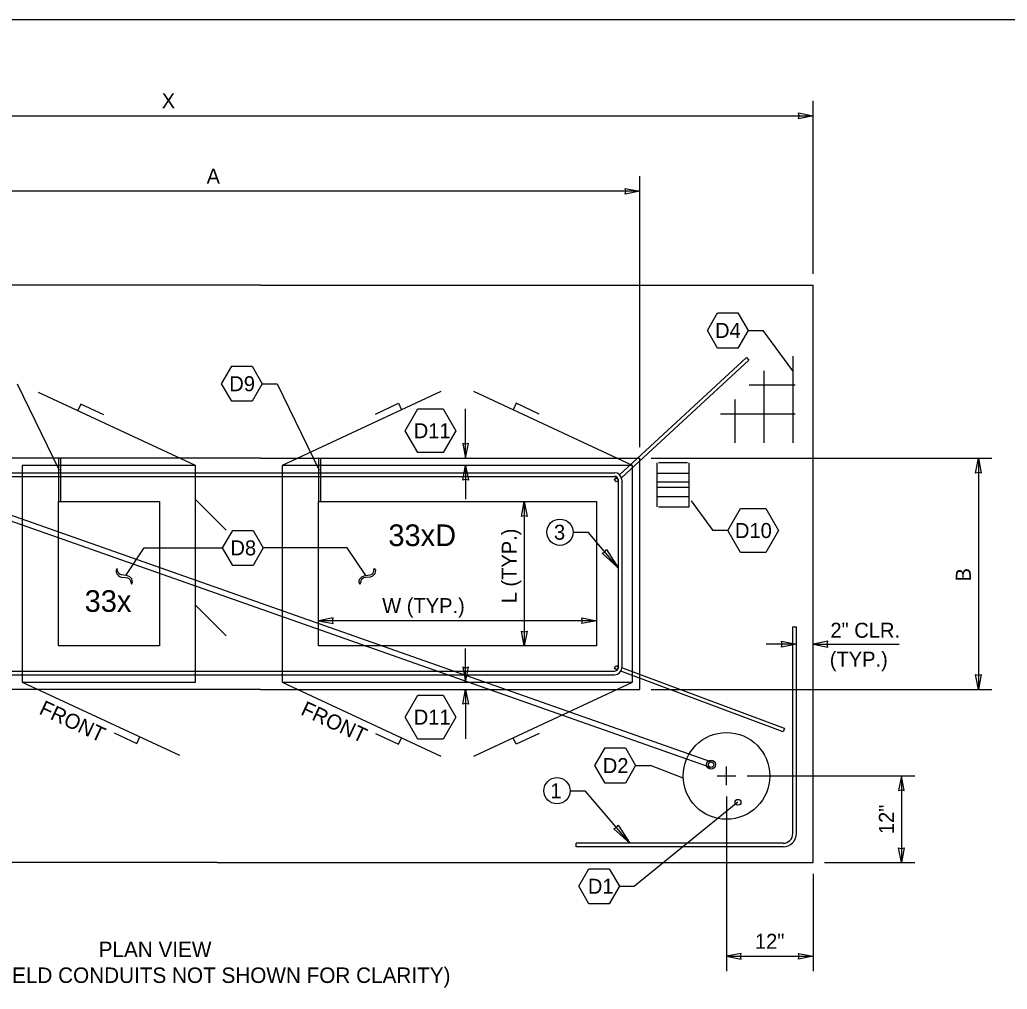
# Model space of a CAD drawing. Extents: x 99862 to 103151, y 100000 to 117076.
# Drawn here: x 100667 to 101719, y 113042 to 114076 of the extents above; entities that cross this region are included whole.
import ezdxf

# ---------------------------------------------------------------- set-up
doc = ezdxf.new("R2010")
doc.units = 0
for name, color, linetype in [('Default', 7, 'Continuous'), ('Level 1', 7, 'Continuous'), ('Level 10', 7, 'Continuous'), ('Level 11', 7, 'Continuous'), ('Level 14', 7, 'Continuous'), ('Level 15', 7, 'Continuous'), ('Level 20', 7, 'Continuous'), ('Level 30', 7, 'Continuous'), ('Level 6', 7, 'Continuous')]:
    doc.layers.add(name, color=color, linetype=linetype)

msp = doc.modelspace()

# ---------------------------------------------------------------- linework, layer by layer
at = {"layer": 'Default'}
for p, q in [((101441.3, 113715.5), (101305.9, 113590.5)), ((101441.3, 113715.5), (101443.9, 113712.7)), ((101443.9, 113712.7), (101308, 113587.3)), ((100442.7, 113592.6), (101300.7, 113592.6)), ((100442.7, 113588.7), (101300.7, 113588.7)), ((101303.1, 113587.9), (101301.3, 113586.3)), ((101304.5, 113584), (101303.9, 113583.5)), ((101304.5, 113584.9), (101304.5, 113384.8)), ((101308.4, 113584.9), (101308.4, 113384.8)), ((101490.6, 113207.9), (101490.6, 113428.3)), ((101490.6, 113428.3), (101494.4, 113428.3)), ((101494.4, 113207.9), (101494.4, 113428.3)), ((100442.7, 113381), (101300.7, 113381)), ((101303.7, 113382.4), (101301.9, 113383)), ((101304.5, 113386.2), (101303.3, 113386.6)), ((101480.3, 113316.3), (101307.4, 113381)), ((101481.7, 113319.9), (101308.4, 113384.7)), ((100442.7, 113377.1), (101300.7, 113377.1)), ((101481.7, 113319.9), (101480.3, 113316.3)), ((101480.3, 113197.6), (101260, 113197.6)), ((101260, 113193.8), (101260, 113197.6)), ((101480.3, 113193.8), (101260, 113193.8))]:
    msp.add_line(p, q, dxfattribs=at)
for centre in [(101302.6, 113584.9), (101302.6, 113384.8)]:
    msp.add_circle(centre, 1.92, dxfattribs=at)
for centre, radius, start, end in [((101300.7, 113584.9), 7.7, 0, 90), ((101300.7, 113584.9), 3.85, 0, 90), ((101300.7, 113384.8), 7.7, 270, 0), ((101300.7, 113384.8), 3.85, 270, 360), ((101480.3, 113207.9), 10.3, 270, 0), ((101480.3, 113207.9), 14.1, 270, 0)]:
    msp.add_arc(centre, radius, start, end, dxfattribs=at)
at = {"layer": 'Level 1'}
for p, q in [((101490.5, 113716.7), (101490.5, 113686)), ((101459.7, 113701.4), (101459.7, 113686)), ((100251, 113684.5), (101402.6, 113278.7)), ((101404.5, 113284.1), (100252.9, 113689.9)), ((101459.7, 113686), (101444.3, 113686)), ((101490.5, 113686), (101459.7, 113686)), ((101459.7, 113686), (101459.7, 113655.2)), ((101490.5, 113686), (101490.5, 113655.2)), ((101493.1, 113686), (101490.5, 113686)), ((101115.8, 113679.1), (100946.7, 113600.3)), ((101319.9, 113600.3), (101150.8, 113679.1)), ((101046.2, 113655.2), (101070.7, 113666.6)), ((101070.7, 113666.6), (101073.9, 113659.6)), ((101196, 113666.6), (101192.8, 113659.6)), ((101220.4, 113655.2), (101196, 113666.6)), ((101428.9, 113670.6), (101428.9, 113655.2)), ((101428.9, 113655.2), (101413.6, 113655.2)), ((101459.7, 113655.2), (101428.9, 113655.2)), ((101428.9, 113655.2), (101428.9, 113624.4)), ((101490.5, 113655.2), (101459.7, 113655.2)), ((101459.7, 113655.2), (101459.7, 113624.4)), ((101490.5, 113655.2), (101490.5, 113624.4)), ((101493.1, 113655.2), (101490.5, 113655.2)), ((100946.7, 113369.4), (101115.8, 113290.6)), ((101150.8, 113290.6), (101319.9, 113369.4)), ((101046.2, 113314.5), (101070.7, 113303.1)), ((101070.7, 113303.1), (101073.9, 113310.1)), ((101196, 113303.1), (101192.8, 113310.1)), ((101220.4, 113314.5), (101196, 113303.1))]:
    msp.add_line(p, q, dxfattribs=at)
for points in [[(99862, 111999.5), (103151, 111999.5), (103151, 114075.5), (99862, 114075.5)], [(100946.7, 113369.4), (101319.9, 113369.4), (101319.9, 113600.3), (100946.7, 113600.3)]]:
    msp.add_lwpolyline(points, close=True, dxfattribs=at)
for centre, radius in [((101403.6, 113281.4), 4.81), ((101403.6, 113281.4), 2.89), ((101432.2, 113241.3), 3.13)]:
    msp.add_circle(centre, radius, dxfattribs=at)
at = {"layer": 'Level 10'}
for p, q in [((101380.2, 113582.7), (101345.6, 113582.7)), ((101380.2, 113576.9), (101345.6, 113576.9))]:
    msp.add_line(p, q, dxfattribs=at)
at = {"layer": 'Level 11'}
for p, q in [((100923.6, 113792.7), (100646.6, 113792.7)), ((100923.6, 113792.7), (101512.3, 113792.7)), ((101512.3, 113177.1), (101512.3, 113792.7)), ((100923.6, 113608), (100646.6, 113608)), ((100923.6, 113608), (101327.6, 113608)), ((101327.6, 113361.7), (101327.6, 113608)), ((100923.6, 113361.7), (100646.6, 113361.7)), ((100923.6, 113361.7), (101327.6, 113361.7)), ((100877.5, 113177.1), (100646.6, 113177.1)), ((100877.5, 113177.1), (101512.3, 113177.1))]:
    msp.add_line(p, q, dxfattribs=at)
for points in [[(100708.2, 113561.8), (100815.9, 113561.8), (100815.9, 113407.9), (100708.2, 113407.9)], [(100985.2, 113561.8), (101281.5, 113561.8), (101281.5, 113407.9), (100985.2, 113407.9)]]:
    msp.add_lwpolyline(points, close=True, dxfattribs=at)
msp.add_circle((101420, 113269.4), 46.2, dxfattribs=at)
at = {"layer": 'Level 14'}
for points in [[(100708.2, 113608), (100708.2, 113561.8)], [(100710.6, 113608), (100710.6, 113561.8)], [(100985.2, 113608), (100985.2, 113561.8)], [(100987.6, 113608), (100987.6, 113561.8)]]:
    msp.add_lwpolyline(points, dxfattribs=at)
at = {"layer": 'Level 15'}
for p, q in [((101512.3, 113804.7), (101512.3, 113989.1)), ((100138.8, 113973.1), (101512.3, 113973.1)), ((101327.6, 113619.8), (101327.6, 113908.7)), ((101327.6, 113892.7), (100415.8, 113892.7)), ((101442.9, 113744.3), (101458.9, 113744.3)), ((101490.5, 113701.4), (101458.9, 113744.3)), ((100664.4, 113687.5), (100709.2, 113595.4)), ((100925.4, 113687.5), (100941.4, 113687.5)), ((100941.4, 113687.5), (100986.2, 113595.4)), ((101142, 113608), (101142, 113660.6)), ((101142, 113600.3), (101142, 113564.5)), ((101339.6, 113608), (101702.7, 113608)), ((101688.3, 113608), (101688.3, 113361.7)), ((101204.6, 113561.8), (101204.6, 113407.9)), ((101382.2, 113562.6), (101405.4, 113531)), ((101256.5, 113529.2), (101272.5, 113529.2)), ((101304.5, 113491.3), (101272.5, 113529.2)), ((101421.4, 113531), (101405.4, 113531)), ((100779.9, 113483.1), (100799.7, 113512.5)), ((100799.7, 113512.5), (100883.2, 113512.5)), ((101016, 113512.5), (100926.5, 113512.5)), ((101035.8, 113483.1), (101016, 113512.5)), ((100770.9, 113490.5), (100769.8, 113488.7)), ((100769.8, 113488.7), (100769.9, 113486.8)), ((100769.9, 113486.8), (100770.5, 113485)), ((100770.5, 113485), (100771.4, 113483.6)), ((100771.3, 113488.1), (100770.9, 113490.5)), ((100771.8, 113486.5), (100771.3, 113488.1)), ((100772.6, 113485.3), (100771.8, 113486.5)), ((100773.6, 113484.4), (100772.6, 113485.3)), ((100775.4, 113483.7), (100773.6, 113484.4)), ((101040.4, 113483.7), (101042.1, 113484.4)), ((101042.1, 113484.4), (101043.1, 113485.3)), ((101043.1, 113485.3), (101043.9, 113486.5)), ((101043.9, 113486.5), (101044.4, 113488.1)), ((101045.3, 113485), (101044.3, 113483.6)), ((101044.4, 113488.1), (101044.8, 113490.5)), ((101044.8, 113490.5), (101046, 113488.7)), ((101045.8, 113486.8), (101045.3, 113485)), ((101046, 113488.7), (101045.8, 113486.8)), ((100771.4, 113483.6), (100772.7, 113482.5)), ((100772.7, 113482.5), (100775.2, 113481.4)), ((100775.2, 113481.4), (100779.6, 113480.8)), ((100777.9, 113483.3), (100775.4, 113483.7)), ((100781.9, 113482.8), (100777.9, 113483.3)), ((100779.6, 113480.8), (100782, 113480.4)), ((100784.2, 113481.8), (100781.9, 113482.8)), ((100782, 113480.4), (100783.4, 113479.8)), ((100783.4, 113479.8), (100784.4, 113478.9)), ((100785.5, 113480.7), (100784.2, 113481.8)), ((100784.4, 113478.9), (100785.2, 113477.4)), ((100785.2, 113477.4), (100786, 113473.8)), ((100786.3, 113479.4), (100785.5, 113480.7)), ((100786, 113473.8), (100787.1, 113475.6)), ((100786.9, 113477.7), (100786.3, 113479.4)), ((100787.1, 113475.6), (100786.9, 113477.7)), ((101028.6, 113475.6), (101028.8, 113477.7)), ((101029.8, 113473.8), (101028.6, 113475.6)), ((101028.8, 113477.7), (101029.4, 113479.4)), ((101029.4, 113479.4), (101030.3, 113480.7)), ((101030.5, 113477.4), (101029.8, 113473.8)), ((101030.3, 113480.7), (101031.5, 113481.8)), ((101031.3, 113478.9), (101030.5, 113477.4)), ((101032.4, 113479.8), (101031.3, 113478.9)), ((101031.5, 113481.8), (101033.8, 113482.8)), ((101033.7, 113480.4), (101032.4, 113479.8)), ((101036.1, 113480.8), (101033.7, 113480.4)), ((101033.8, 113482.8), (101037.8, 113483.3)), ((101040.5, 113481.4), (101036.1, 113480.8)), ((101037.8, 113483.3), (101040.4, 113483.7)), ((101043, 113482.5), (101040.5, 113481.4)), ((101044.3, 113483.6), (101043, 113482.5)), ((101281.5, 113434.9), (100985.2, 113434.9)), ((101142, 113369.4), (101142, 113405.2)), ((101494.4, 113409.8), (101462.4, 113409.8)), ((101512.3, 113409.8), (101603.9, 113409.8)), ((101142, 113361.7), (101142, 113309.1)), ((101339.6, 113361.7), (101702.7, 113361.7)), ((101323.1, 113280.4), (101339.1, 113280.4)), ((101373.9, 113266.9), (101339.1, 113280.4)), ((101420, 113259.4), (101420, 113279.4)), ((101410, 113269.4), (101430, 113269.4)), ((101442, 113269.4), (101620.8, 113269.4)), ((101606.3, 113269.4), (101606.3, 113177.1)), ((101253.4, 113253.6), (101269.4, 113253.6)), ((101316.9, 113197.6), (101269.5, 113253.6)), ((101420, 113247.4), (101420, 113061.1)), ((101432.2, 113241.3), (101321.9, 113151.8)), ((101524.3, 113177.1), (101620.8, 113177.1)), ((101512.3, 113165.1), (101512.3, 113061.1)), ((101305.9, 113151.8), (101321.9, 113151.8)), ((101420, 113077.1), (101512.3, 113077.1))]:
    msp.add_line(p, q, dxfattribs=at)
for points in [[(101512.3, 113973.1), (101496.6, 113970), (101497.3, 113973.1), (101496.6, 113976.2)], [(101327.6, 113892.7), (101311.9, 113889.6), (101312.6, 113892.7), (101311.9, 113895.7)], [(101142, 113608), (101145.1, 113623.7), (101142, 113623), (101139, 113623.7)], [(101142, 113600.3), (101145.1, 113584.6), (101142, 113585.3), (101139, 113584.6)], [(101688.3, 113608), (101691.3, 113592.2), (101688.3, 113593), (101685.2, 113592.2)], [(101204.6, 113561.8), (101207.7, 113546.1), (101204.6, 113546.8), (101201.6, 113546.1)], [(101304.5, 113491.3), (101287.5, 113506.8), (101290.5, 113508), (101292.1, 113510.7)], [(100985.2, 113434.9), (101000.9, 113431.8), (101000.2, 113434.9), (101000.9, 113438)], [(101281.5, 113434.9), (101265.7, 113431.8), (101266.5, 113434.9), (101265.7, 113438)], [(101204.6, 113407.9), (101201.6, 113423.6), (101204.6, 113422.9), (101207.7, 113423.6)], [(101494.4, 113409.8), (101478.7, 113406.7), (101479.4, 113409.8), (101478.7, 113412.9)], [(101512.3, 113409.8), (101528, 113406.7), (101527.3, 113409.8), (101528, 113412.9)], [(101142, 113369.4), (101145.1, 113385.2), (101142, 113384.4), (101139, 113385.2)], [(101688.3, 113361.7), (101685.2, 113377.5), (101688.3, 113376.7), (101691.3, 113377.5)], [(101142, 113361.7), (101145.1, 113346), (101142, 113346.7), (101139, 113346)], [(101606.3, 113269.4), (101603.2, 113253.7), (101606.3, 113254.4), (101609.4, 113253.7)], [(101316.9, 113197.6), (101299.8, 113213.1), (101302.8, 113214.3), (101304.4, 113217)], [(101606.3, 113177.1), (101603.2, 113192.8), (101606.3, 113192.1), (101609.4, 113192.8)], [(101420, 113077.1), (101435.7, 113074), (101435, 113077.1), (101435.7, 113080.1)], [(101512.3, 113077.1), (101496.6, 113074), (101497.3, 113077.1), (101496.6, 113080.1)]]:
    msp.add_lwpolyline(points, close=True, dxfattribs=at)
at = {"layer": 'Level 20'}
for points in [[(101399.6, 113744.3), (101410.4, 113763), (101432.1, 113763), (101442.9, 113744.3), (101432.1, 113725.5), (101410.4, 113725.5), (101399.6, 113744.3)], [(100882.1, 113687.5), (100892.9, 113706.3), (100914.6, 113706.3), (100925.4, 113687.5), (100914.6, 113668.8), (100892.9, 113668.8), (100882.1, 113687.5)], [(101077.7, 113637.4), (101091.3, 113660.8), (101118.3, 113660.8), (101131.8, 113637.4), (101118.3, 113614), (101091.3, 113614), (101077.7, 113637.4)], [(101421.4, 113531), (101435, 113554.4), (101462, 113554.4), (101475.5, 113531), (101462, 113507.6), (101435, 113507.6), (101421.4, 113531)], [(100883.2, 113512.5), (100894.1, 113531.2), (100915.7, 113531.2), (100926.5, 113512.5), (100915.7, 113493.7), (100894.1, 113493.7), (100883.2, 113512.5)], [(101077.7, 113332.1), (101091.3, 113355.6), (101118.3, 113355.6), (101131.8, 113332.1), (101118.3, 113308.7), (101091.3, 113308.7), (101077.7, 113332.1)], [(101279.8, 113280.4), (101290.6, 113299.2), (101312.3, 113299.2), (101323.1, 113280.4), (101312.3, 113261.7), (101290.6, 113261.7), (101279.8, 113280.4)], [(101262.6, 113151.8), (101273.4, 113170.5), (101295.1, 113170.5), (101305.9, 113151.8), (101295.1, 113133), (101273.4, 113133), (101262.6, 113151.8)]]:
    msp.add_lwpolyline(points, dxfattribs=at)
for centre in [(101242.5, 113529.2), (101239.4, 113253.6)]:
    msp.add_circle(centre, 14, dxfattribs=at)
at = {"layer": 'Level 30'}
for p, q in [((101378.3, 113603.3), (101347.5, 113603.3)), ((101345.6, 113592.1), (101380.2, 113592.1)), ((101345.6, 113567.4), (101380.2, 113567.4)), ((101347.5, 113556.2), (101378.3, 113556.2)), ((101378.3, 113556.2), (101380.2, 113556.2))]:
    msp.add_line(p, q, dxfattribs=at)
for points in [[(101345.6, 113603.3), (101345.6, 113556.2), (101345.6, 113556.2)], [(101380.2, 113556.2), (101380.2, 113556.2), (101380.2, 113603.3), (101380.2, 113603.3)]]:
    msp.add_lwpolyline(points, dxfattribs=at)
at = {"layer": 'Level 6'}
for p, q in [((100854.4, 113600.3), (100687, 113678.3)), ((100732.2, 113665.7), (100729, 113658.8)), ((100756.6, 113654.4), (100732.2, 113665.7)), ((100887, 113531.5), (100854.4, 113564.1)), ((100887, 113418.9), (100854.4, 113451.5)), ((100669.7, 113369.4), (100837.1, 113291.4)), ((100767.5, 113315.3), (100791.9, 113304)), ((100791.9, 113304), (100795.1, 113310.9))]:
    msp.add_line(p, q, dxfattribs=at)
msp.add_lwpolyline([(100669.7, 113369.4), (100854.4, 113369.4), (100854.4, 113600.3), (100669.7, 113600.3)], close=True, dxfattribs=at)

# ---------------------------------------------------------------- texts
at = {"layer": 'Level 1'}
msp.add_text('33xD', height=23.09, dxfattribs=at).set_placement((101059.8, 113514.4))
at = {"layer": 'Level 20'}
for s, height, p in [('X', 16, (100818.3, 113981.1)), ('A', 16, (100866.1, 113900.7)), ('D4', 16, (101407.8, 113736.3)), ('D9', 16, (100890.3, 113679.5)), ('D11', 16, (101086.8, 113629.4)), ('3', 16, (101236.2, 113521.2)), ('D10', 16, (101429, 113523)), ('D8', 16, (100891.5, 113504.5)), ('W (TYP.)', 16, (101053.2, 113442.9)), ('2" CLR.', 16, (101530.7, 113416.7)), ('(TYP.)', 16, (101530, 113385.8)), ('D11', 16, (101086.8, 113324.1)), ('D2', 16, (101288.2, 113272.4)), ('1', 16, (101232.3, 113245.6)), ('D1', 16, (101272.3, 113143.8)), ('12"', 16, (101450.3, 113085.1)), ('PLAN VIEW', 16.5, (100751.1, 113076.2)), ('(UTILITY AND  FIELD CONDUITS NOT SHOWN FOR CLARITY)', 16.5, (100484.8, 113048.7))]:
    msp.add_text(s, height=height, dxfattribs=at).set_placement(p)
for s, rotation, p in [('L (TYP.)', 90, (101196.6, 113453.4)), ('B', 90, (101680.3, 113476.7)), ('FRONT', 335, (100686.6, 113336)), ('FRONT', 335, (100965.3, 113335.2)), ('12"', 90, (101598.3, 113207.4))]:
    msp.add_text(s, height=16, rotation=rotation, dxfattribs=at).set_placement(p)
at = {"layer": 'Level 6'}
msp.add_text('33x', height=23.09, dxfattribs=at).set_placement((100736.2, 113444.3))

doc.saveas('drawing.dxf')
